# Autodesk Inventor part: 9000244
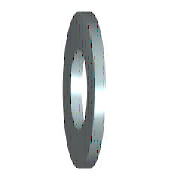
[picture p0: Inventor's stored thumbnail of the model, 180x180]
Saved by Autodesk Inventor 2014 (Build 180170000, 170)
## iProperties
IsCustomPart: 1
Created: 2011-02
Material: Steel, Mild
Description: WASHER, FLAT 1/4"
Document SubType Name: Modeling
Standard: ANSI B18.22.1
Designer: Dave Walker
Standard Revision: 1998
Standards Organization: ANSI
Language: en-US
Size Designation: 1/4 - wide - Type A
Categories: <MemberInstance><Categories><Category DisplayName="Fasteners" InternalName="e4da775c-781d-43d5-af7c-5136215cf5a6" Mnemonic="FSTN"><Category DisplayName="Washers
Density: 7.86 g/cm^3
Part Number: 9000244
Mass: 2.90249 g
Surface Area: 5.85138 cm^2
Volume: 0.369274 cm^3
Appearance: Steel
Author: Dave Walker
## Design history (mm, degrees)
sketch "Sketch"
  geometry: C1 r 9.322 at (0, 0); C2 r 3.962 at (0, 0); 1 further point
  constraints: 2 centre point, 2 coincident
  dimensions: "d0" = 7.9248 diameter of C2 (= SD1); "d1" = 18.6436 diameter of C1 (= SD2)
extrude "Body" new body sketch "Sketch" distance "d2" = 1.651 (= SD); taper "d3" = 0 deg
workaxis "Work Axis1"
workplane "Work Plane1"
body "Solid1"
other parameters: "SD1" = 7.9248 [user parameter; used in 1 equation term], "SD2" = 18.6436 [user parameter; used in 1 equation term], "SD" = 1.651 [user parameter; used in 1 equation term], "d4" = 0, "d5" = 0, "d6" = 0, "d7" = 0, "NND" = 6.35 [user parameter]
